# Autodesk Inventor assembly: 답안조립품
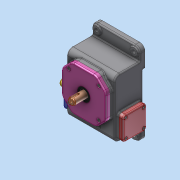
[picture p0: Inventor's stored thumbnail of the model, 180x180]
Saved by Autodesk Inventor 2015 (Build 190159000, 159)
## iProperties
Created: 2026-02
Part Number: 답안조립품
Document SubType Name: Assembly
Designer: Administrator
Author: Administrator
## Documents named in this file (14)
- C:\Users\Administrator\Desktop\760203V1004\답안조립품.iam
- C:\Users\Administrator\Desktop\760203V1004\본체.ipt
- C:\Users\Administrator\Desktop\760203V1004\6각 구멍붙이 볼트 M4x10.ipt
- C:\Users\Administrator\Desktop\760203V1004\6각 구멍붙이 볼트 M5x10.ipt
- C:\Users\Administrator\Desktop\760203V1004\뒷커버.ipt
- C:\Users\Administrator\Desktop\760203V1004\앞커버.ipt
- C:\Users\Administrator\Desktop\760203V1004\오일 실 17 32 8.ipt
- C:\Users\Administrator\Desktop\760203V1004\웜 샤프트.ipt
- C:\Users\Administrator\Desktop\760203V1004\웜 휠 커버.ipt
- C:\Users\Administrator\Desktop\760203V1004\웜 휠.ipt
- C:\Users\Administrator\Desktop\760203V1004\축.ipt
- C:\Users\Administrator\Desktop\760203V1004\칼라.ipt
- C:\Users\Administrator\Desktop\760203V1004\테이퍼 롤러 베어링 30203.ipt
- C:\Users\Administrator\Desktop\760203V1004\평행 키 5x5x16.ipt
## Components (12 placed, 2 different names)
1. 6각 구멍붙이 볼트 M4x10:1
2. 6각 구멍붙이 볼트 M5x10:1
3. 6각 구멍붙이 볼트 M4x10:2
4. 6각 구멍붙이 볼트 M4x10:3
5. 6각 구멍붙이 볼트 M4x10:4
6. 6각 구멍붙이 볼트 M4x10:5
7. 6각 구멍붙이 볼트 M4x10:6
8. 6각 구멍붙이 볼트 M4x10:7
9. 6각 구멍붙이 볼트 M4x10:8
10. 6각 구멍붙이 볼트 M5x10:2
11. 6각 구멍붙이 볼트 M5x10:3
12. 6각 구멍붙이 볼트 M5x10:4
